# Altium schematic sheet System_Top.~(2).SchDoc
size A3; SheetNumber: 1; SheetTotal: 4; PageSetup: Record=PageOptions¦CenterHorizontal=True¦CenterVertical=True¦PrintScale=1.01¦XCorrection=1.00¦YCorrection=1.00¦PrintKind=1¦BorderSize=5000000¦LeftOffset=0¦BottomOffset=0¦Orientation=2¦PaperLength=1000¦PaperWidth=1000¦Scale=100¦PaperSource=7¦PrintQuality=600¦MediaType=1¦DitherType=10¦PaperKind=A3¦PrintScaleMode=1
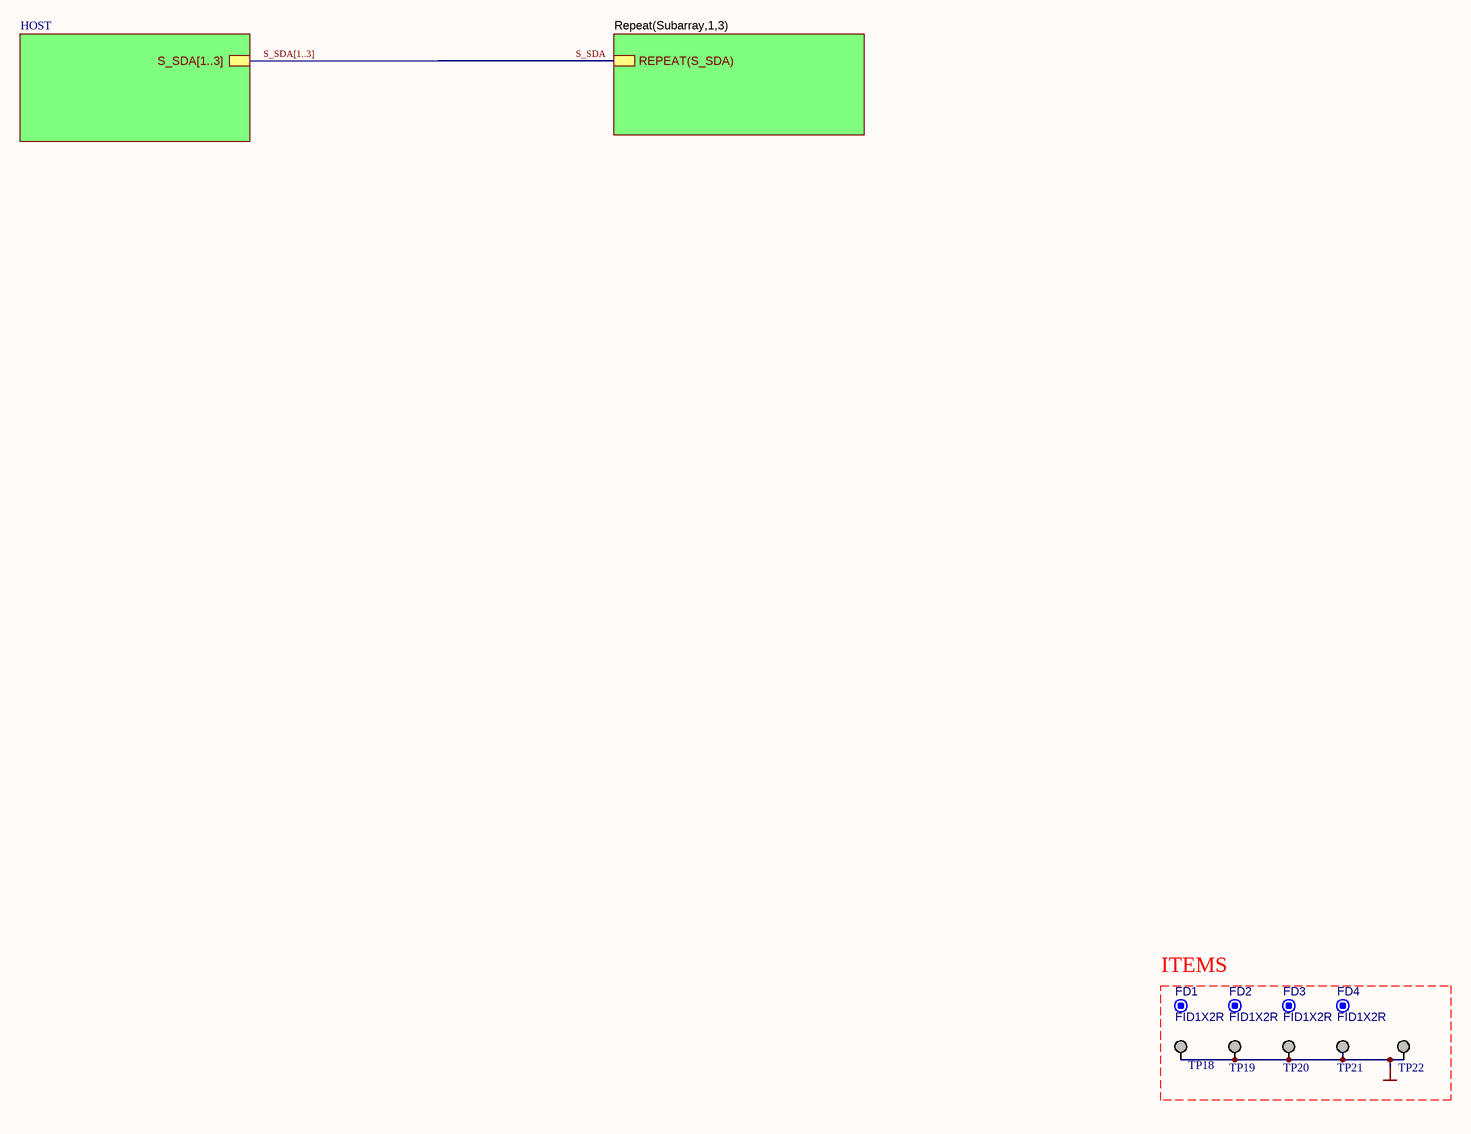
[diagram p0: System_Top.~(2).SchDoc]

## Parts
FD1  FID1X2R  [FID1X2R]  (no BOM)
FD2  FID1X2R  [FID1X2R]  (no BOM)
FD3  FID1X2R  [FID1X2R]  (no BOM)
FD4  FID1X2R  [FID1X2R]  (no BOM)
TP18  TP_DC_1MM WZ  [TP_DC_1mm]  (value not drawn)
TP19  TP_DC_1MM WZ  [TP_DC_1mm]  (value not drawn)
TP20  TP_DC_1MM WZ  [TP_DC_1mm]  (value not drawn)
TP21  TP_DC_1MM WZ  [TP_DC_1mm]  (value not drawn)
TP22  TP_DC_1MM WZ  [TP_DC_1mm]  (value not drawn)

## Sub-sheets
HOST = HOST.SchDoc: S_SDA[1..3]
Repeat(Subarray,1,3) = Subarray.SchDoc: REPEAT(S_SDA)

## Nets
GND: TP18.1 TP19.1 TP20.1 TP21.1 TP22.1

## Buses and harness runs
bus S_SDA[1..3] = sheet HOST/S_SDA[1..3]

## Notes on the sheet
- ITEMS

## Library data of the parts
FD1-FD4 = CMP-00028-00005-4: Fiducial - Round 1x2mm; Barcode: 999999
TP18-TP22 = CMP-00030-3: DC, 1mm Test Point, SMT; Barcode: 999999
